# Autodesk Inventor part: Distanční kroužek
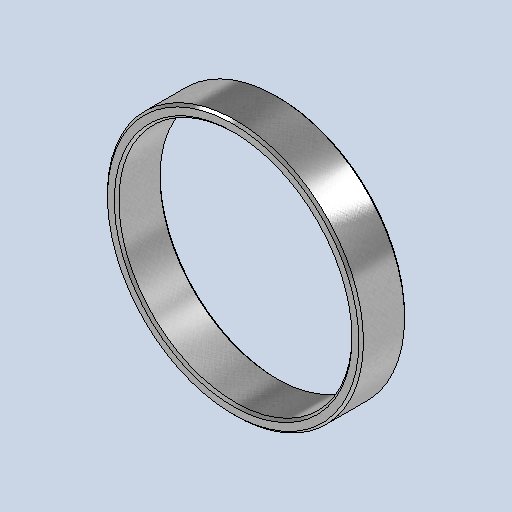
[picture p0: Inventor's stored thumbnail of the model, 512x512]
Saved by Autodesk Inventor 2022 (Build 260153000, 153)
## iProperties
Created: 2025-05
Part Number: Distanční kroužek
Material: Všeobecné
Document SubType Name: Modeling
Designer: jbart
Density: 1 g/cm^3
Appearance: Broušená
Mass: 4.11784 g
Surface Area: 40.0497 cm^2
Volume: 4.11784 cm^3
Author: jbart
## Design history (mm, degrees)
sketch "Náčrt1"
  geometry: C1 r 25.5 at (0, 0); C2 r 28 at (0, 0); 1 further point
  constraints: 2 centre point, 2 coincident
  dimensions: "d0" = 51 diameter of C1; "d1" = 56 diameter of C2
extrude "Vysunutí1" new body sketch "Náčrt1" distance "d2" = 10; taper "d3" = 0 deg
chamfer "Zkosení1" distance "d4" = 0.5; stored, may be unused: second distance "d5" = 2, angle "d6" = 45 deg
node "Těleso1"
